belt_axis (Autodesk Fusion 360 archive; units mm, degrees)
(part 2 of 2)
sketch "Sketch1" plane through (0, 0, 0) normal (0, 1, 0) x axis (1, 0, 0)
  line L1 (8, 0) -> (0, 0)
  line L2 (8, -7) -> (8, 0)
  line L3 (6.3662, -7) -> (8, -7)
  line L4 (6.3662, -14.7) -> (6.3662, -7)
  line L5 (8, -14.7) -> (6.3662, -14.7)
  line L6 (8, -16) -> (8, -14.7)
  line L7 (2.5, -16) -> (8, -16)
  line L8 (2.5, 0) -> (2.5, -16)
  line L9 (0, -3) -> (0, 0)
  circle C1 centre (0, -3) radius 1.5
  point P1 (0, 0)
  point P2 (0, 0)
  point P10 (2.5, 0)
  point P4 (8, -7)
  point P12 (0, 0)
  point P11 (0, -3)
  point P13 (0, -3)
  point P3 (8, 0)
  point P7 (8, -14.7)
  point P8 (8, -16)
  coincident P1 P2
  horizontal L1
  perpendicular L1 L2
  perpendicular L2 L3
  perpendicular L3 L4
  perpendicular L4 L5
  perpendicular L5 L6
  perpendicular L4 L7
  coincident L1 P10
  perpendicular L1 L8
  coincident P4 L6
  coincident P1 P12
  coincident P11 P13
  vertical L9
  dimension "d1" distance P1 L8 = 2.5 (= "( 5 / 2 ) * 1 mm")
  dimension "d2" distance P1 L2 = 8 (= "( 16 / 2 ) * 1 mm")
  dimension "d3" distance P3 P4 = 7
  dimension "d4" distance P1 L4 = 6.3662 (= "( 20 * 2 / PI ) * 1 mm / 2")
  dimension "d5" distance P7 P8 = 1.3
  dimension "d6" distance P3 L7 = 16
  dimension "d8" diameter C1 = 3
  dimension "d9" distance P12 P13 = 3
revolve "Revolve1" sketch "Sketch1" AlongAngle 360
extrude "Extrude1" cut sketch "Sketch1" profile of C1 against normal blind 17

design "HW_M3x16-SHCS"
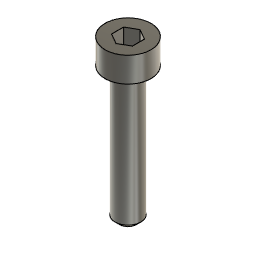
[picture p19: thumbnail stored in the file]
sketch "Sketch1" plane through (0, 0, 0) normal (0, 1, 0) x axis (1, 0, 0)
  line L1 (0, 16) -> (0, -3)
  line L2 (1.05, 16) -> (0, 16)
  line L3 (1.55, 15.5) -> (1.05, 16)
  line L4 (1.55, 0) -> (1.55, 15.5)
  line L5 (2.75, 0) -> (1.55, 0)
  line L6 (2.75, -3) -> (2.75, 0)
  line L7 (0, -3) -> (2.75, -3)
  point P1 (0, 0)
  point P4 (1.05, 16)
  point P5 (1.55, 15.5)
  point P3 (0, 16)
  point P7 (2.75, 0)
  point P8 (2.75, -3)
  point P2 (0, -3)
  vertical L1
  perpendicular L1 L2
  perpendicular L2 L4
  perpendicular L4 L5
  perpendicular L5 L6
  horizontal L7
  coincident P1 L1
  coincident P1 L5
  dimension "d1" distance P1 L2 = 16
  dimension "d2" angle L2 L3 = 45
  dimension "d3" distance P4 P5 = 0.5
  dimension "d4" distance P3 L4 = 1.55 (= "( 3.1 / 2 ) * 1 mm")
  dimension "d5" distance P7 P8 = 3
  dimension "d6" distance P2 P8 = 2.75 (= "( 5.5 / 2 ) * 1 mm")
revolve "Revolve1" sketch "Sketch1" AlongAngle 360
sketch "Sketch2" plane through (0, 0, 3) normal (0, 0, 1) x axis (-1, 0, 0)
  line L1 (0, -1.4434) -> (-1.25, -0.7217)
  line L2 (1.25, -0.7217) -> (0, -1.4434)
  line L3 (1.25, 0.7217) -> (1.25, -0.7217)
  line L4 (0, 1.4434) -> (1.25, 0.7217)
  line L5 (-1.25, 0.7217) -> (0, 1.4434)
  line L6 (-1.25, -0.7217) -> (-1.25, 0.7217)
  circle C1 centre (0, 0) radius 2.75
  point P1 (0, 0)
  point P9 (0, 0)
  point P5 (1.25, -0.7217)
  coincident P1 P9
  vertical L6
  dimension "d8" distance P5 L6 = 2.5
extrude "Extrude1" cut sketch "Sketch2" profile of L1 L2 L3 L4 L5 L6 against normal blind 2

design "belt_idler" references "HW_M5x20-FHCS", "HW_M5-Washer", "PP_BRNG_625F-5x16x5", "HW_M5x10-FHCS"
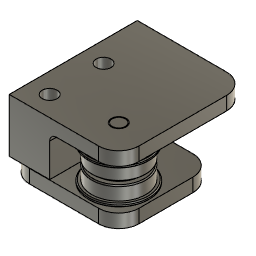
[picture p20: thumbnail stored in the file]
sketch "Sketch1" plane through (0, 0, 0) normal (0, 0, 1) x axis (1, 0, 0)
  line L1 (0, 0) -> (23.5, 0)
  line L2 (0, 29) -> (0, -9)
  line L3 (32.5, 29) -> (0, 29)
  line L4 (32.5, -9) -> (32.5, 29)
  line L5 (0, -9) -> (32.5, -9)
  line L6 (5, 29) -> (5, -9)
  line L7 (12, 29) -> (12, -9)
  line L8 (6, 13) -> (6, -3)
  line L9 (0, 19) -> (12, 19)
  line L10 (32.5, 19) -> (12, 19)
  circle C1 centre (23.5, 0) radius 8.5
  circle C2 centre (23.5, 0) radius 7.5
  circle C3 centre (23.5, 0) radius 2.55
  circle C4 centre (23.5, 0) radius 3.55
  circle C5 centre (23.5, 0) radius 2.2
  circle C6 centre (6, -3) radius 2.2
  circle C7 centre (6, -3) radius 5
  circle C8 centre (6, -3) radius 2.75
  circle C9 centre (6, 13) radius 2.75
  circle C10 centre (6, 13) radius 2.2
  circle C11 centre (6, 13) radius 5
  point P2 (23.5, 0)
  point P3 (23.5, 0)
  point P4 (23.5, 0)
  point P1 (0, 0)
  point P5 (0, 0)
  point P6 (15, 0)
  point P7 (0, -9)
  point P11 (0, -9)
  point P12 (23.5, 0)
  point P15 (5, -9)
  point P16 (5, 29)
  point P18 (12, -9)
  point P19 (12, 29)
  point P22 (6, -3)
  point P26 (6, -3)
  point P24 (6, 13)
  point P27 (6, 13)
  point P28 (12, 19)
  point P29 (0, 19)
  point P30 (6, 5)
  point P31 (32.5, 19)
  point P13 (23.5, 0)
  point P9 (32.5, 29)
  point P10 (32.5, -9)
  point P21 (6, -3)
  point P23 (6, 13)
  coincident P2 P3
  coincident P2 P4
  coincident P1 P5
  horizontal L1
  coincident C1 P6
  coincident L1 P6
  perpendicular L2 L3
  perpendicular L3 L4
  perpendicular L4 L5
  coincident P7 P11
  coincident P2 P12
  concentric C2 C3
  coincident P1 L2
  vertical L2
  concentric C1 C4
  coincident L5 P15
  coincident L3 P16
  perpendicular L3 L6
  concentric C1 C5
  coincident L5 P18
  coincident L3 P19
  perpendicular L3 L7
  concentric C6 C7
  concentric C6 C8
  concentric C9 C10
  concentric C9 C11
  equal C7 C11
  coincident P22 P26
  coincident P24 P27
  vertical L8
  equal C6 C10
  equal C8 C9
  coincident L7 P28
  coincident L2 P29
  perpendicular L2 L9
  midpoint L8 P30
  coincident L4 P31
  perpendicular L4 L10
  dimension "d2" distance P1 P6 = 15
  dimension "d38" distance C1 C2 = 1
  dimension "d39" diameter C2 = 15
  dimension "d40" diameter C3 = 5.1
  dimension "d41" distance L4 P13 = 9
  dimension "d42" distance L5 P13 = 9
  dimension "d43" distance C3 C4 = 1
  dimension "d44" distance P7 P15 = 5
  dimension "d46" distance P9 P10 = 38
  dimension "d48" diameter C5 = 4.4
  dimension "d63" distance P6 L7 = 3
  dimension "d64" diameter C7 = 10
  dimension "d65" diameter C6 = 4.4
  dimension "d66" diameter C8 = 5.5
  dimension "d67" distance P7 P22 = 6
  dimension "d68" distance P7 P21 = 6
  dimension "d69" distance P26 P27 = 16
  dimension "d78" distance P23 L9 = 6
extrude "Extrude1" new body sketch "Sketch1" profile of L2 L3 L4 L5 C3 C4 L6 C5 L7 C6 C8 C9 C10 L9 L10 along normal blind 4 bodies "belt_idler_body"
extrude "Extrude2" sketch "Sketch1" profile of L2 L3 L5 L6 blind -20
extrude "Extrude4" add sketch "Sketch1" profile of C3 C4 C5 against normal blind 0.5
chamfer "Chamfer5" distance 0.4 distance 1
component_insert "Component Insert3"
joint "Assemble3" alignAngle 0 alignOffsetX 0 alignOffsetY 0 alignOffsetZ 0
component_insert "Component Insert4"
joint "Assemble4" alignAngle 0 alignOffsetX 0 alignOffsetY 0 alignOffsetZ 0
component_insert "Component Insert5"
joint "Assemble5" alignAngle 0 alignOffsetX 0 alignOffsetY 0 alignOffsetZ 0
extrude "Extrude5" add sketch "Sketch1" profile of L3 L5 L6 L7 C6 C8 C9 C10 to an object
sketch "Sketch2" plane through (0, 0, 0) normal (-1, 0, 0) x axis (0, -1, 0)
  line L1 (9, 4) -> (9, -16)
  line L2 (-29, 4) -> (9, 4)
  line L3 (-29, -16) -> (-29, 4)
  line L4 (9, -16) -> (-29, -16)
  line L5 (-29, -6) -> (9, -6)
  line L6 (-5, -6) -> (-5, 0)
  circle C1 centre (-23, -6) radius 2.75
  circle C2 centre (-23, -6) radius 5.25
  circle C3 centre (-5, -6) radius 2.75
  circle C4 centre (-5, -6) radius 5.25
  point P6 (9, -6)
  point P7 (-29, -6)
  point P8 (-23, -6)
  point P10 (-5, -6)
  point P12 (-5, 0)
  point P13 (-5, 0)
  point P11 (-5, -6)
  point P14 (-5, -6)
  point P4 (-29, 4)
  point P9 (-23, -6)
  midpoint L1 P6
  midpoint L3 P7
  coincident L5 P8
  concentric C1 C2
  coincident L5 P10
  concentric C3 C4
  equal C2 C4
  equal C1 C3
  coincident P12 P13
  coincident P11 P14
  vertical L6
  dimension "d17" distance P4 P9 = 6
  dimension "d19" diameter C1 = 5.5
  dimension "d20" diameter C2 = 10.5
extrude "Extrude3" cut sketch "Sketch2" profile of C1 C3 no distance stored
extrude "Extrude6" cut sketch "Sketch2" profile of C1 C2 C3 C4 no distance stored from offset -5
chamfer "Chamfer3" distance 2.5
extrude "Extrude7" sketch "Sketch1" profile of L6 C6 C10 to an object
extrude "Extrude8" sketch "Sketch1" profile of L2 L5 L6 L7 C6 C8 C9 C10 L9 blind 4.1
offset_faces "OffsetFaces1" distance -0.1
extrude "Extrude9" sketch "Sketch1" profile of L2 L4 L5 C3 C4 L6 L7 C8 C9 L9 L10 blind 4 bodies "belt_idler_cap"
extrude "Extrude10" sketch "Sketch1" profile of C3 C4 blind 0.5
chamfer "Chamfer4" distance 2.5
fillet "Fillet4" radius 1
fillet "Fillet5" radius 6
fillet "Fillet6" radius 6
fillet "Fillet7" radius 2
component_insert "Component Insert6"
joint "Assemble6" alignAngle 0 alignOffsetX 0 alignOffsetY 0 alignOffsetZ 0
component_insert "Component Insert7"
component_insert "Component Insert8"
joint "Assemble7" alignAngle 0 alignOffsetX 0 alignOffsetY 0 alignOffsetZ 0
joint "Assemble8" alignAngle 0 alignOffsetX 0 alignOffsetY 0 alignOffsetZ 0
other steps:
joint_origin "JointOrigin2"
joint_origin "JointOrigin3"
joint_origin "JointOrigin4"
joint_origin "JointOrigin5"
named bodies: "belt_idler_body", "belt_idler_cap"

design "belt_clip"
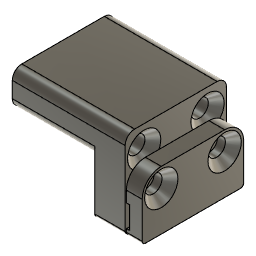
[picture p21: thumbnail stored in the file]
sketch "Sketch1" plane through (0, 0, 0) normal (0, 0, 1) x axis (1, 0, 0)
  line L1 (0, 16) -> (0, 0)
  line L2 (41, 16) -> (0, 16)
  line L3 (41, 0) -> (41, 16)
  line L4 (0, 0) -> (41, 0)
  line L5 (37, 16) -> (37, 0)
  line L6 (35.6, 0) -> (35.6, 16)
  line L7 (36, 16) -> (36, 0)
  line L8 (1, 16) -> (1, 0)
  line L9 (21, 16) -> (21, 0)
  line L10 (37, 1) -> (35.6, 1)
  line L11 (36.25, 0.7402) -> (36.25, 1)
  line L12 (38, 1) -> (37, 1)
  line L13 (38, 0) -> (38, 1)
  line L14 (38, 16) -> (38, 1)
  line L15 (26, 0) -> (26, 16)
  arc A1 centre (36.445, 0) radius 0.555 clockwise from (36.6882, 0.4989) to (37, 0)
  arc A2 centre (36.25, -0.4) radius 1 clockwise from (36.3804, 0.5915) to (36.6882, 0.4989)
  arc A3 centre (36.4, 0.7402) radius 0.15 clockwise from (36.3804, 0.5915) to (36.25, 0.7402)
  point P1 (0, 0)
  point P2 (0, 0)
  point P6 (0, 0)
  point P7 (37, 0)
  point P8 (37, 16)
  point P9 (35.6, 16)
  point P10 (35.6, 0)
  point P11 (36, 0)
  point P12 (36, 16)
  point P13 (1, 0)
  point P14 (1, 16)
  point P15 (21, 0)
  point P16 (21, 16)
  point P17 (35.6, 1)
  point P18 (37, 1)
  point P19 (36.25, 1)
  point P27 (38, 0)
  point P28 (38, 16)
  point P29 (26, 16)
  point P30 (26, 0)
  point P3 (0, 16)
  point P4 (41, 16)
  point P24 (36.25, -0.4)
  point P26 (38, 1)
  coincident P1 P2
  vertical L1
  perpendicular L1 L2
  perpendicular L2 L3
  perpendicular L3 L4
  coincident P1 P6
  coincident L4 P7
  coincident L2 P8
  perpendicular L2 L5
  coincident L2 P9
  coincident L4 P10
  perpendicular L4 L6
  coincident L4 P11
  coincident L2 P12
  perpendicular L2 L7
  coincident L4 P13
  perpendicular L4 L8
  coincident L2 P14
  coincident L4 P15
  coincident L2 P16
  perpendicular L2 L9
  coincident L6 P17
  perpendicular L5 L10
  coincident L5 P18
  coincident L10 P19
  perpendicular L10 L11
  tangent L5 A1
  tangent A1 A2
  tangent L11 A3
  tangent A2 A3
  perpendicular L5 L12
  perpendicular L4 L13
  coincident L4 P27
  coincident L2 P28
  perpendicular L2 L14
  coincident L2 P29
  perpendicular L4 L15
  coincident L4 P30
  dimension "d1" distance P2 P3 = 16
  dimension "d2" distance P4 P8 = 4
  dimension "d3" distance P7 P10 = 1.4
  dimension "d4" distance P1 L8 = 1
  dimension "d5" distance P14 P16 = 20
  dimension "d6" distance P12 P16 = 15
  dimension "d7" distance P10 P11 = 0.4
  dimension "d8" distance P7 P18 = 1
  dimension "d9" radius A1 = 0.555
  dimension "d10" radius A2 = 1
  dimension "d11" radius A3 = 0.15
  dimension "d12" distance L4 P24 = 0.4
  dimension "d13" distance P11 L11 = 0.25
  dimension "d22" distance P18 P26 = 1
  dimension "d36" distance P16 L15 = 5
extrude "Extrude1" new body sketch "Sketch1" profile of L1 L2 L4 L6 L15 blind 11 from offset 1 bodies "belt_clip_bod"
extrude "Extrude2" new body sketch "Sketch1" profile of L4 L5 L10 L11 A1 A2 A3 L12 L13 blind -7 from offset -6.5 bodies "belt_clip_cap"
mirror "Mirror1" mirrorStitchTolerance 0.1
rectangular_pattern "R-Pattern1" uSpaceDistance 2 vSpaceDistance 0
combine "Combine1"
extrude "Extrude3" sketch "Sketch1" profile of L2 L3 L4 L5 L7 L10 L11 A1 A2 A3 L12 L13 L14 blind -2
extrude "Extrude4" sketch "Sketch1" profile of L2 L3 L4 L13 L14 to an object
extrude "Extrude5" sketch "Sketch1" profile of L2 L3 L4 L5 L7 L10 L11 A1 A2 A3 L12 L13 L14 to an object
extrude "Extrude6" sketch "Sketch1" profile of L2 L4 L6 L15 to an object
sketch "Sketch2" plane through (0, 0, 0) normal (-1, 0, 0) x axis (0, -1, 0)
  line L1 (0, 1) -> (-16, 1)
  line L2 (0, 12) -> (0, 1)
  line L3 (-16, 12) -> (0, 12)
  line L4 (-16, 1) -> (-16, 12)
  circle C1 centre (-10, 5) radius 2.75
  circle C2 centre (-10, 5) radius 5
  point P1 (0, 0)
  point P6 (-10, 5)
  concentric C1 C2
  dimension "d40" distance P1 P6 = 10
  dimension "d41" distance P1 P6 = 5
  dimension "d42" diameter C1 = 5.5
  dimension "d61" diameter C2 = 10
sketch "Sketch3" plane through (41, 0, 0) normal (1, 0, 0) x axis (0, 1, 0)
  line L1 (0, -15.5) -> (0, 12)
  line L2 (16, -15.5) -> (0, -15.5)
  line L3 (16, 12) -> (16, -15.5)
  line L4 (0, 12) -> (16, 12)
  line L5 (0, 3) -> (16, 3)
  circle C1 centre (10, -3) radius 2.2
  circle C2 centre (10, -3) radius 5
  circle C3 centre (10, -3) radius 2.75
  point P9 (16, 3)
  point P10 (0, 3)
  point P1 (0, 0)
  point P8 (10, -3)
  point P4 (16, -15.5)
  point P6 (10, -3)
  concentric C1 C2
  concentric C1 C3
  coincident L3 P9
  coincident L1 P10
  perpendicular L1 L5
  dimension "d49" diameter C2 = 10
  dimension "d50" diameter C3 = 5.5
  dimension "d51" diameter C1 = 4.4
  dimension "d52" distance P1 P8 = 3
  dimension "d54" distance P4 P6 = 6
  dimension "d55" distance P8 P9 = 6
extrude "Extrude8" cut sketch "Sketch3" profile of C1 to an object
extrude "Extrude9" cut sketch "Sketch3" profile of L1 L3 L4 C1 C3 L5 against normal blind 5
chamfer "Chamfer1" distance 2.5
extrude "Extrude10" cut sketch "Sketch2" profile of C1 to an object
chamfer "Chamfer2" distance 2.5
fillet "Fillet1" radius 6
fillet "Fillet2" radius 1
fillet "Fillet3" radius 3
mirror "Mirror3" mirrorStitchTolerance 0.1
named bodies: "belt_clip_bod", "belt_clip_cap"

design "HW_M5x20-FHCS"
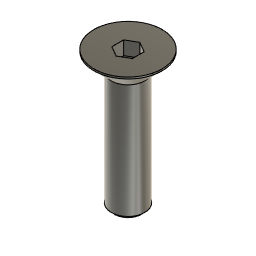
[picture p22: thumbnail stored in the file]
sketch "Sketch1" plane through (0, 0, 0) normal (0, 1, 0) x axis (1, 0, 0)
  line L1 (0, 20) -> (0, 0)
  line L2 (1.95, 20) -> (0, 20)
  line L3 (2.45, 19.5) -> (1.95, 20)
  line L4 (2.45, 2.8) -> (2.45, 19.5)
  line L5 (5, 0.25) -> (2.45, 2.8)
  line L6 (5, 0) -> (5, 0.25)
  line L7 (0, 0) -> (5, 0)
  point P1 (0, 0)
  point P2 (0, 0)
  point P9 (0, 0)
  point P3 (0, 20)
  point P4 (1.95, 20)
  point P8 (5, 0)
  point P7 (5, 0.25)
  coincident P1 P2
  vertical L1
  perpendicular L1 L2
  perpendicular L2 L4
  parallel L3 L5
  parallel L4 L6
  perpendicular L6 L7
  coincident P1 P9
  dimension "d1" distance P3 L4 = 2.45 (= "( 4.9 / 2 ) * 1 mm")
  dimension "d3" angle L2 L3 = 45
  dimension "d5" distance P4 L4 = 0.5
  dimension "d6" distance P2 P3 = 20
  dimension "d7" distance P8 P9 = 5 (= "( 10 / 2 ) * 1 mm")
  dimension "d9" distance P7 P8 = 0.25
revolve "Revolve1" sketch "Sketch1" AlongAngle 360
sketch "Sketch2" plane through (0, 0, 0) normal (0, 0, 1) x axis (-1, 0, 0)
  line L1 (0, -1.7321) -> (-1.5, -0.866)
  line L2 (1.5, -0.866) -> (0, -1.7321)
  line L3 (1.5, 0.866) -> (1.5, -0.866)
  line L4 (0, 1.7321) -> (1.5, 0.866)
  line L5 (-1.5, 0.866) -> (0, 1.7321)
  line L6 (-1.5, -0.866) -> (-1.5, 0.866)
  circle C1 centre (0, 0) radius 5
  point P1 (0, 0)
  point P9 (0, 0)
  coincident P1 P9
  vertical L6
  dimension "d12" distance L3 L6 = 3
extrude "Extrude1" cut sketch "Sketch2" profile of L1 L2 L3 L4 L5 L6 against normal blind 2

design "PP_ACTU_N17-Stepper"
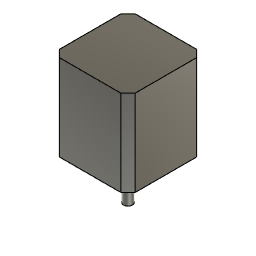
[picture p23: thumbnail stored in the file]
description: Nema 17 Stepper, 48mm Length Preferred, 5mm Shaft
sketch "Sketch1" plane through (0, 0, 0) normal (0, 0, 1) x axis (1, 0, 0)
  line L1 (-21.15, 21.15) -> (21.15, 21.15)
  line L2 (-21.15, -21.15) -> (-21.15, 21.15)
  line L3 (21.15, -21.15) -> (-21.15, -21.15)
  line L4 (21.15, 21.15) -> (21.15, -21.15)
  line L5 (-21.15, -21.15) -> (21.15, 21.15)
  line L6 (21.15, -21.15) -> (-21.15, 21.15)
  line L7 (15.5, 15.5) -> (-15.5, 15.5)
  line L8 (15.5, -15.5) -> (15.5, 15.5)
  line L9 (-15.5, -15.5) -> (15.5, -15.5)
  line L10 (-15.5, 15.5) -> (-15.5, -15.5)
  circle C1 centre (0, 0) radius 11
  circle C2 centre (-15.5, 15.5) radius 1.5
  circle C3 centre (-15.5, -15.5) radius 1.5
  circle C4 centre (15.5, -15.5) radius 1.5
  circle C5 centre (15.5, 15.5) radius 1.5
  circle C6 centre (0, 0) radius 2.5
  point P6 (0, 0)
  point P1 (0, 0)
  point P7 (0, 0)
  point P10 (15.5, -15.5)
  point P8 (-15.5, 15.5)
  point P9 (15.5, 15.5)
  point P12 (-15.5, 15.5)
  point P11 (-15.5, -15.5)
  point P13 (-15.5, -15.5)
  point P14 (15.5, -15.5)
  point P15 (15.5, 15.5)
  point P2 (21.15, 21.15)
  point P3 (-21.15, 21.15)
  perpendicular L1 L2
  parallel L1 L3
  parallel L2 L4
  horizontal L1
  coincident L5 P6
  coincident L6 P6
  coincident P1 P6
  equal L1 L2
  coincident P6 P7
  horizontal L7
  vertical L8
  horizontal L9
  vertical L10
  coincident L6 P10
  coincident L6 P8
  coincident L5 P9
  coincident P8 P12
  coincident P11 P13
  coincident P10 P14
  coincident P9 P15
  equal C2 C5
  equal C2 C3
  equal C2 C4
  concentric C1 C6
  dimension "d1" distance P2 P3 = 42.3
  dimension "d2" diameter C1 = 22
  dimension "d3" distance P8 P9 = 31
  dimension "d4" diameter C2 = 3
  dimension "d5" diameter C6 = 5
  dimension "d19" alignAngle = 0
  dimension "d20" alignOffsetX = 0
  dimension "d21" alignOffsetY = 0
  dimension "d22" alignOffsetZ = 0
  dimension "d23" alignAngle = 180
  dimension "d24" alignOffsetX = 0
  dimension "d25" alignOffsetY = 0
  dimension "d26" alignOffsetZ = 0
extrude "Extrude1" new body sketch "Sketch1" profile of L1 L2 L3 L4 C1 C2 C3 C4 C5 C6 along normal blind 48
extrude "Extrude2" cut sketch "Sketch1" profile of C2 C3 C4 C5 along normal blind 5
extrude "Extrude3" add sketch "Sketch1" profile of C1 C6 against normal blind 2
extrude "Extrude4" add sketch "Sketch1" profile of C6 against normal blind 24
chamfer "Chamfer1" distance 4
